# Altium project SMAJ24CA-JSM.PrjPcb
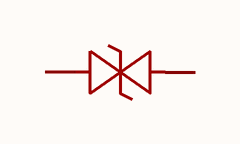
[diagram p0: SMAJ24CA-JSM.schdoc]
1 sheet, 1 parts. Net scope: global (net labels, ports and power ports of the same name join across sheets).

## Sheet SMAJ24CA-JSM.schdoc
size 127 x 101 mm

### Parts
D?  smaj24ca-jsm  [SMA_L4.3-W2.6-LS5.2-BI]  (value not drawn)

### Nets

Not connected (* = marked no-connect by the designer): D? 1(C) 2(A)

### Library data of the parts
D? = smaj24ca-jsm: 极性:双向;反向截止电压(Vrwm):24V;钳位电压:38.9V;峰值脉冲电流(Ipp):10.3A@10/1000us;峰值脉冲功率(Ppp):400W;击穿电压(VBR):29.5V;; Manufacturer: JSMSEMI(杰盛微); AddInBom: yes; ModelId: a802d5185fc344359be61e832a1aeec0; ModelTransform: 194.8815,102.362,0,0,0,0,0,0,0; Polarity: 双向; Reverse Stand-Off Voltage (Vrwm): 24V; Clamping Voltage: 38.9V; Peak Pulse Power Dissipation (Ppp): 400W; Voltage - Breakdown: 29.5V; Reverse Leakage Current (Ir): 1uA; Number of Channels: 单路; Type: TVS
